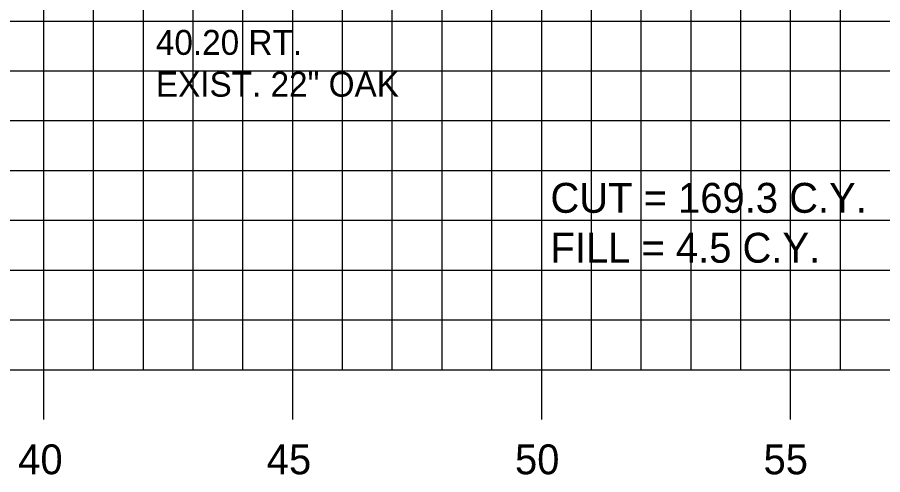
# Model space of a CAD drawing. Extents: x 853563 to 853733, y 366268 to 366378.
# Drawn here: x 853685.24 to 853702.62, y 366325.13 to 366334.31 of the extents above; entities that cross this region are included whole.
import ezdxf

# ---------------------------------------------------------------- set-up
doc = ezdxf.new("R2010")
doc.units = 0
for name, color, linetype in [('ANNOTATION', 7, 'Continuous'), ('D_Text_Monospaced', 7, 'Continuous'), ('H_V ANNOTATION', 7, 'Continuous'), ('MAJOR', 7, 'Continuous'), ('MINOR', 7, 'Continuous')]:
    doc.layers.add(name, color=color, linetype=linetype)

msp = doc.modelspace()

# ---------------------------------------------------------------- linework, layer by layer
at = {"layer": 'MAJOR'}
for p, q in [((853685.768, 366327.236), (853685.768, 366347.236)), ((853690.768, 366327.236), (853690.768, 366347.236)), ((853695.768, 366327.236), (853695.768, 366347.236)), ((853700.768, 366327.236), (853700.768, 366347.236)), ((853575.768, 366332.236), (853715.768, 366332.236)), ((853575.768, 366327.236), (853715.768, 366327.236)), ((853575.768, 366327.236), (853715.768, 366327.236)), ((853685.768, 366326.234), (853685.768, 366327.236)), ((853690.768, 366326.234), (853690.768, 366327.236)), ((853695.768, 366326.234), (853695.768, 366327.236)), ((853700.768, 366326.234), (853700.768, 366327.236))]:
    msp.add_line(p, q, dxfattribs=at)
at = {"layer": 'MINOR'}
for p, q in [((853686.768, 366327.236), (853686.768, 366347.236)), ((853687.768, 366327.236), (853687.768, 366347.236)), ((853688.768, 366327.236), (853688.768, 366347.236)), ((853689.768, 366327.236), (853689.768, 366347.236)), ((853691.768, 366327.236), (853691.768, 366347.236)), ((853692.768, 366327.236), (853692.768, 366347.236)), ((853693.768, 366327.236), (853693.768, 366347.236)), ((853694.768, 366327.236), (853694.768, 366347.236)), ((853696.768, 366327.236), (853696.768, 366347.236)), ((853697.768, 366327.236), (853697.768, 366347.236)), ((853698.768, 366327.236), (853698.768, 366347.236)), ((853699.768, 366327.236), (853699.768, 366347.236)), ((853701.768, 366327.236), (853701.768, 366347.236)), ((853575.768, 366334.236), (853715.768, 366334.236)), ((853575.768, 366333.236), (853715.768, 366333.236)), ((853575.768, 366331.236), (853715.768, 366331.236)), ((853575.768, 366330.236), (853715.768, 366330.236)), ((853575.768, 366329.236), (853715.768, 366329.236)), ((853575.768, 366328.236), (853715.768, 366328.236))]:
    msp.add_line(p, q, dxfattribs=at)

# ---------------------------------------------------------------- texts
at = {"layer": 'ANNOTATION'}
for s, p in [('CUT = 169.3 C.Y.', (853695.944, 366330.386)), ('FILL = 4.5 C.Y.', (853695.944, 366329.384))]:
    msp.add_text(s, height=0.6, dxfattribs=at).set_placement(p)
at = {"layer": 'D_Text_Monospaced'}
for s, height, p in [('40.20 RT.', 0.5, (853688.019, 366333.557)), ('EXIST. 22" OAK', 0.49998, (853688.019, 366332.717))]:
    msp.add_text(s, height=height, dxfattribs=at).set_placement(p)
at = {"layer": 'H_V ANNOTATION'}
for s, p in [('40', (853685.254, 366325.136)), ('45', (853690.246, 366325.136)), ('50', (853695.232, 366325.136)), ('55', (853700.224, 366325.136))]:
    msp.add_text(s, height=0.6, dxfattribs=at).set_placement(p)

doc.saveas('drawing.dxf')
